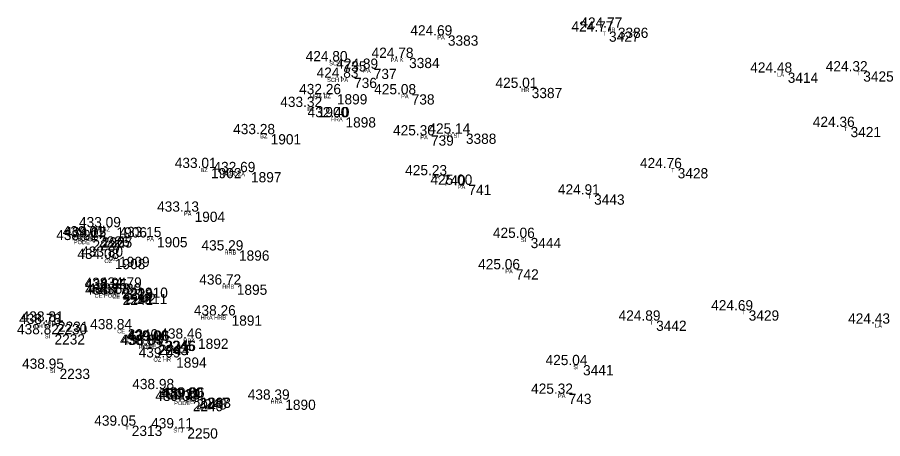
# Model space of a CAD drawing. Extents: x -639390 to -639075, y -1138747 to -1138358.
# Drawn here: x -639327.9 to -639264.6, y -1138469.3 to -1138438.4 of the extents above; entities that cross this region are included whole.
import ezdxf

# ---------------------------------------------------------------- set-up
doc = ezdxf.new("R2010")
doc.units = 0
for name, color, linetype in [('Vrstva 11', 7, 'Continuous'), ('Vrstva 12', 7, 'Continuous'), ('Vrstva 13', 7, 'Continuous'), ('Vrstva 57', 7, 'Continuous')]:
    doc.layers.add(name, color=color, linetype=linetype)

msp = doc.modelspace()

# ---------------------------------------------------------------- linework, layer by layer
at = {"layer": 'Vrstva 11'}
for p, q in [((-639284.23, -1138439.15), (-639284.23, -1138439.15)), ((-639296.68, -1138439.72), (-639296.68, -1138439.72)), ((-639284.88, -1138439.43), (-639284.88, -1138439.43)), ((-639304.32, -1138441.61), (-639304.32, -1138441.61)), ((-639299.52, -1138441.36), (-639299.52, -1138441.36)), ((-639302.11, -1138442.16), (-639302.11, -1138442.16)), ((-639271.79, -1138442.44), (-639271.79, -1138442.44)), ((-639266.26, -1138442.35), (-639266.26, -1138442.35)), ((-639303.55, -1138442.82), (-639303.55, -1138442.82)), ((-639290.54, -1138443.56), (-639290.54, -1138443.56)), ((-639304.81, -1138444.02), (-639304.81, -1138444.02)), ((-639299.33, -1138444.03), (-639299.33, -1138444.03)), ((-639306.21, -1138444.96), (-639306.21, -1138444.96)), ((-639304.18, -1138445.71), (-639304.18, -1138445.71)), ((-639309.66, -1138446.95), (-639309.66, -1138446.95)), ((-639295.36, -1138446.91), (-639295.36, -1138446.91)), ((-639267.19, -1138446.42), (-639267.19, -1138446.42)), ((-639297.92, -1138447.04), (-639297.92, -1138447.04)), ((-639314.03, -1138449.43), (-639314.03, -1138449.43)), ((-639279.85, -1138449.44), (-639279.85, -1138449.44)), ((-639311.1, -1138449.73), (-639311.1, -1138449.73)), ((-639297.06, -1138449.96), (-639297.06, -1138449.96)), ((-639295.18, -1138450.66), (-639295.18, -1138450.66)), ((-639285.97, -1138451.37), (-639285.97, -1138451.37)), ((-639315.23, -1138452.63), (-639315.23, -1138452.63)), ((-639320.95, -1138453.77), (-639320.95, -1138453.77)), ((-639322.23, -1138454.44), (-639322.23, -1138454.44)), ((-639322.03, -1138454.51), (-639322.03, -1138454.51)), ((-639322.02, -1138454.5), (-639322.02, -1138454.5)), ((-639317.98, -1138454.49), (-639317.98, -1138454.49)), ((-639290.62, -1138454.55), (-639290.62, -1138454.55)), ((-639322.71, -1138454.71), (-639322.71, -1138454.71)), ((-639311.98, -1138455.47), (-639311.98, -1138455.47)), ((-639321.07, -1138456.09), (-639321.07, -1138456.09)), ((-639320.76, -1138455.93), (-639320.76, -1138455.93)), ((-639291.7, -1138456.85), (-639291.7, -1138456.85)), ((-639320.54, -1138458.22), (-639320.54, -1138458.22)), ((-639320.5, -1138458.32), (-639320.5, -1138458.32)), ((-639319.42, -1138458.19), (-639319.42, -1138458.19)), ((-639312.14, -1138457.97), (-639312.14, -1138457.97)), ((-639320.5, -1138458.71), (-639320.5, -1138458.71)), ((-639320.29, -1138458.63), (-639320.29, -1138458.63)), ((-639319.46, -1138458.65), (-639319.46, -1138458.65)), ((-639312.52, -1138460.23), (-639312.52, -1138460.23)), ((-639274.65, -1138459.86), (-639274.65, -1138459.86)), ((-639325.33, -1138460.86), (-639325.33, -1138460.86)), ((-639325.24, -1138460.68), (-639325.24, -1138460.68)), ((-639281.43, -1138460.61), (-639281.43, -1138460.61)), ((-639264.62, -1138460.83), (-639264.62, -1138460.83)), ((-639320.13, -1138461.24), (-639320.13, -1138461.24)), ((-639325.49, -1138461.61), (-639325.49, -1138461.61)), ((-639317.44, -1138462.08), (-639317.44, -1138462.08)), ((-639317.37, -1138462.09), (-639317.37, -1138462.09)), ((-639314.98, -1138461.93), (-639314.98, -1138461.93)), ((-639317.94, -1138462.39), (-639317.94, -1138462.39)), ((-639317.83, -1138462.38), (-639317.83, -1138462.38)), ((-639316.58, -1138463.31), (-639316.58, -1138463.31)), ((-639286.78, -1138463.87), (-639286.78, -1138463.87)), ((-639325.12, -1138464.14), (-639325.12, -1138464.14)), ((-639317.05, -1138465.63), (-639317.05, -1138465.63)), ((-639287.84, -1138465.97), (-639287.84, -1138465.97)), ((-639315.36, -1138466.5), (-639315.36, -1138466.5)), ((-639315.11, -1138466.37), (-639315.11, -1138466.37)), ((-639314.89, -1138466.26), (-639314.89, -1138466.26)), ((-639314.8, -1138466.25), (-639314.8, -1138466.25)), ((-639308.59, -1138466.4), (-639308.59, -1138466.4)), ((-639319.83, -1138468.31), (-639319.83, -1138468.31)), ((-639315.76, -1138468.5), (-639315.76, -1138468.5))]:
    msp.add_line(p, q, dxfattribs=at)

# ---------------------------------------------------------------- texts
at = {"layer": 'Vrstva 12'}
for s, p in [('424.77 ', (-639287.349, -1138439.43)), ('424.77 ', (-639286.699, -1138439.15)), ('424.69 ', (-639299.149, -1138439.72)), ('424.78 ', (-639301.989, -1138441.36)), ('424.80 ', (-639306.819, -1138441.61)), ('424.89 ', (-639304.579, -1138442.16)), ('424.48 ', (-639274.259, -1138442.44)), ('424.32 ', (-639268.729, -1138442.35)), ('424.83 ', (-639306.019, -1138442.82)), ('425.01 ', (-639292.915, -1138443.56)), ('432.26 ', (-639307.296, -1138444.02)), ('425.08 ', (-639301.799, -1138444.03)), ('433.32 ', (-639308.679, -1138444.96)), ('432.40 ', (-639306.679, -1138445.71)), ('424.36 ', (-639269.676, -1138446.42)), ('433.28 ', (-639312.129, -1138446.95)), ('425.30 ', (-639300.419, -1138447.04)), ('425.14 ', (-639297.829, -1138446.91)), ('433.01 ', (-639316.405, -1138449.43)), ('424.76 ', (-639282.336, -1138449.44)), ('432.69 ', (-639313.569, -1138449.73)), ('425.23 ', (-639299.529, -1138449.96)), ('425.00 ', (-639297.679, -1138450.66)), ('424.91 ', (-639288.345, -1138451.37)), ('433.13 ', (-639317.699, -1138452.63)), ('433.09 ', (-639323.419, -1138453.77)), ('439.01 ', (-639324.605, -1138454.44)), ('439.02 ', (-639324.499, -1138454.51)), ('434.15 ', (-639324.49, -1138454.5)), ('433.15 ', (-639320.45, -1138454.49)), ('425.06 ', (-639293.106, -1138454.55)), ('438.91 ', (-639325.085, -1138454.71)), ('433.80 ', (-639323.259, -1138455.93)), ('435.29 ', (-639314.449, -1138455.47)), ('434.08 ', (-639323.539, -1138456.09)), ('425.06 ', (-639294.186, -1138456.85)), ('438.94 ', (-639323.009, -1138458.22)), ('438.85 ', (-639322.97, -1138458.32)), ('434.79 ', (-639321.889, -1138458.19)), ('436.72 ', (-639314.609, -1138457.97)), ('438.77 ', (-639322.969, -1138458.71)), ('438.83 ', (-639322.759, -1138458.63)), ('435.39 ', (-639321.929, -1138458.65)), ('438.26 ', (-639315.006, -1138460.23)), ('424.69 ', (-639277.119, -1138459.86)), ('438.78 ', (-639327.799, -1138460.86)), ('438.81 ', (-639327.615, -1138460.68)), ('424.89 ', (-639283.899, -1138460.61)), ('424.43 ', (-639267.089, -1138460.83)), ('438.82 ', (-639327.959, -1138461.61)), ('438.84 ', (-639322.599, -1138461.24)), ('439.00 ', (-639319.939, -1138462.08)), ('439.06 ', (-639319.856, -1138462.09)), ('438.46 ', (-639317.466, -1138461.93)), ('438.84 ', (-639320.409, -1138462.39)), ('438.85 ', (-639320.3, -1138462.38)), ('439.09 ', (-639319.049, -1138463.31)), ('438.95 ', (-639327.59, -1138464.14)), ('425.04 ', (-639289.249, -1138463.87)), ('438.98 ', (-639319.519, -1138465.63)), ('425.32 ', (-639290.309, -1138465.97)), ('439.09 ', (-639317.829, -1138466.5)), ('439.14 ', (-639317.579, -1138466.37)), ('439.20 ', (-639317.389, -1138466.26)), ('439.06 ', (-639317.286, -1138466.25)), ('438.39 ', (-639311.059, -1138466.4)), ('439.05 ', (-639322.3, -1138468.31)), ('439.11 ', (-639318.135, -1138468.5))]:
    msp.add_text(s, height=0.75, dxfattribs=at).set_placement(p)
at = {"layer": 'Vrstva 13'}
for s, p in [(' 3386', (-639284.23, -1138439.9)), (' 3383', (-639296.68, -1138440.47)), (' 3427', (-639284.88, -1138440.18)), (' 735', (-639304.32, -1138442.36)), (' 3384', (-639299.52, -1138442.11)), (' 737', (-639302.11, -1138442.91)), (' 3414', (-639271.79, -1138443.19)), (' 3425', (-639266.26, -1138443.1)), (' 736', (-639303.55, -1138443.57)), (' 3387', (-639290.54, -1138444.31)), (' 1899', (-639304.81, -1138444.77)), (' 738', (-639299.33, -1138444.78)), (' 1900', (-639306.21, -1138445.71)), (' 1898', (-639304.18, -1138446.46)), (' 1901', (-639309.66, -1138447.7)), (' 3388', (-639295.36, -1138447.66)), (' 3421', (-639267.19, -1138447.17)), (' 739', (-639297.92, -1138447.79)), (' 1902', (-639314.03, -1138450.18)), (' 3428', (-639279.85, -1138450.19)), (' 1897', (-639311.1, -1138450.48)), (' 740', (-639297.06, -1138450.71)), (' 741', (-639295.18, -1138451.41)), (' 3443', (-639285.97, -1138452.12)), (' 1904', (-639315.23, -1138453.38)), (' 1906', (-639320.95, -1138454.52)), (' 2226', (-639322.23, -1138455.19)), (' 2225', (-639322.03, -1138455.26)), (' 1907', (-639322.02, -1138455.25)), (' 1905', (-639317.98, -1138455.24)), (' 3444', (-639290.62, -1138455.3)), (' 2227', (-639322.71, -1138455.46)), (' 1896', (-639311.98, -1138456.22)), (' 1908', (-639321.07, -1138456.84)), (' 1909', (-639320.76, -1138456.68)), (' 742', (-639291.7, -1138457.6)), (' 2228', (-639320.54, -1138458.97)), (' 2229', (-639320.5, -1138459.07)), (' 1910', (-639319.42, -1138458.94)), (' 1895', (-639312.14, -1138458.72)), (' 2241', (-639320.5, -1138459.46)), (' 2242', (-639320.29, -1138459.38)), (' 1911', (-639319.46, -1138459.4)), (' 1891', (-639312.52, -1138460.98)), (' 3429', (-639274.65, -1138460.61)), (' 2230', (-639325.33, -1138461.61)), (' 2231', (-639325.24, -1138461.43)), (' 3442', (-639281.43, -1138461.36)), (' 2240', (-639320.13, -1138461.99)), (' 2232', (-639325.49, -1138462.36)), (' 2245', (-639317.44, -1138462.83)), (' 2246', (-639317.37, -1138462.84)), (' 1892', (-639314.98, -1138462.68)), (' 2243', (-639317.94, -1138463.14)), (' 2244', (-639317.83, -1138463.13)), (' 1894', (-639316.58, -1138464.06)), (' 3441', (-639286.78, -1138464.62)), (' 2233', (-639325.12, -1138464.89)), (' 2239', (-639317.05, -1138466.38)), (' 743', (-639287.84, -1138466.72)), (' 2249', (-639315.36, -1138467.25)), (' 2248', (-639315.11, -1138467.12)), (' 2247', (-639314.89, -1138467.01)), (' 1893', (-639314.8, -1138467)), (' 1890', (-639308.59, -1138467.15)), (' 2313', (-639319.83, -1138469.06)), (' 2250', (-639315.76, -1138469.25))]:
    msp.add_text(s, height=0.75, dxfattribs=at).set_placement(p)
at = {"layer": 'Vrstva 57'}
for s, p in [('HR', (-639284.719, -1138439.45)), ('PA', (-639297.18, -1138440.02)), ('T', (-639285.08, -1138439.73)), ('SCH', (-639305.095, -1138441.91)), ('PA K', (-639300.595, -1138441.66)), ('PA', (-639302.61, -1138442.46)), ('LA', (-639272.29, -1138442.74)), ('T', (-639266.46, -1138442.65)), ('SCH PA', (-639305.25, -1138443.12)), ('HR', (-639291.029, -1138443.86)), ('HRA BZ', (-639306.499, -1138444.32)), ('PA', (-639299.83, -1138444.33)), ('BZ', (-639306.699, -1138445.26)), ('HRA', (-639304.98, -1138446.01)), ('BZ', (-639310.149, -1138447.25)), ('HR SI', (-639296.698, -1138447.21)), ('T', (-639267.39, -1138446.72)), ('PA', (-639298.42, -1138447.34)), ('BZ', (-639314.519, -1138449.73)), ('T', (-639280.05, -1138449.74)), ('HRB OZA', (-639313.1, -1138450.03)), ('PA', (-639297.56, -1138450.26)), ('PA', (-639295.68, -1138450.96)), ('T', (-639286.17, -1138451.67)), ('PA', (-639315.73, -1138452.93)), ('PA BZ', (-639322.339, -1138454.07)), ('K PODE', (-639323.917, -1138454.74)), ('BZ OZ', (-639323.409, -1138454.8)), ('BZ', (-639322.519, -1138454.81)), ('PA', (-639318.48, -1138454.79)), ('SI', (-639291.058, -1138454.85)), ('PODE', (-639323.797, -1138455.01)), ('HRB', (-639312.769, -1138455.77)), ('OZ', (-639321.559, -1138456.39)), ('OZ', (-639321.249, -1138456.23)), ('PA', (-639292.2, -1138457.15)), ('PODE OBR', (-639322.829, -1138458.52)), ('PODE CH', (-639322.475, -1138458.62)), ('OZ', (-639319.909, -1138458.49)), ('HRB', (-639312.929, -1138458.27)), ('CE PODE', (-639322.277, -1138458.93)), ('CE', (-639320.988, -1138459.01)), ('OZ', (-639319.949, -1138458.95)), ('HRA HRB', (-639314.509, -1138460.53)), ('T', (-639274.85, -1138460.16)), ('CH SI', (-639326.668, -1138461.16)), ('OBR', (-639326.029, -1138460.98)), ('T', (-639281.63, -1138460.91)), ('LA', (-639265.12, -1138461.13)), ('CE', (-639320.618, -1138461.54)), ('SI', (-639325.928, -1138461.91)), ('K', (-639317.615, -1138462.38)), ('K', (-639317.545, -1138462.39)), ('HRA', (-639315.78, -1138462.23)), ('PODE', (-639319.027, -1138462.69)), ('PODE', (-639318.917, -1138462.68)), ('OZ HR', (-639317.969, -1138463.61)), ('SI', (-639287.218, -1138464.17)), ('SI', (-639325.558, -1138464.44)), ('CE', (-639317.537, -1138465.93)), ('PA', (-639288.34, -1138466.27)), ('PODE', (-639316.448, -1138466.8)), ('PL', (-639315.585, -1138466.67)), ('OZ', (-639315.289, -1138466.55)), ('K', (-639315.065, -1138466.56)), ('HRA', (-639309.39, -1138466.7)), ('T', (-639320.03, -1138468.61)), ('STJ', (-639316.51, -1138468.8))]:
    msp.add_text(s, height=0.3, dxfattribs=at).set_placement(p)

doc.saveas('drawing.dxf')
